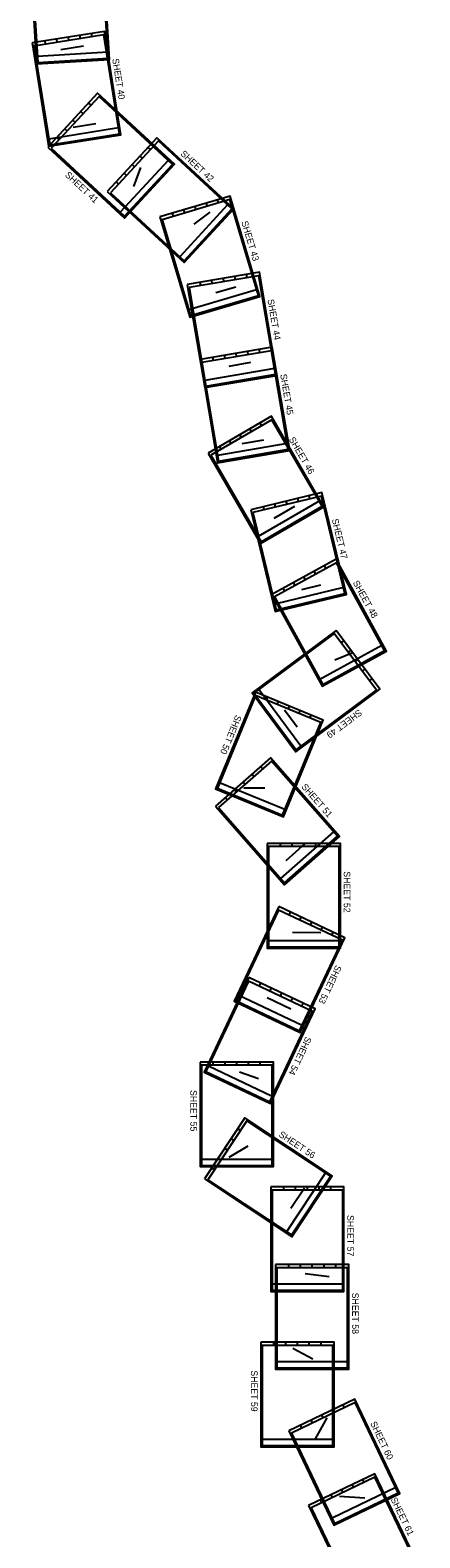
# Model space of a CAD drawing. Extents: x 518852 to 589310, y 1937169 to 2155394.
# Drawn here: x 550218 to 565119, y 1993000 to 2050636 of the extents above; entities that cross this region are included whole.
import ezdxf

# ---------------------------------------------------------------- set-up
doc = ezdxf.new("R2010")
doc.units = 0
doc.layers.add('Level 1', color=7, linetype='Continuous')
doc.layers.add('Level 58', color=7, linetype='Continuous')

msp = doc.modelspace()

# ---------------------------------------------------------------- linework, layer by layer
at = {"layer": 'Level 1'}
for p, q in [((550391, 2050518), (550441, 2050521)), ((550809, 2050100), (550790, 2050224)), ((551254, 2050171), (551234, 2050294)), ((551698, 2050242), (551679, 2050365)), ((552143, 2050312), (552123, 2050436)), ((552587, 2050383), (552567, 2050506)), ((553164, 2050238), (553213, 2050241)), ((550386, 2049577), (550436, 2049585)), ((550419, 2050069), (550469, 2050072)), ((553191, 2049789), (550496, 2049623)), ((552759, 2049486), (552756, 2049536)), ((553102, 2050009), (553152, 2050017)), ((553173, 2049565), (553222, 2049573)), ((550457, 2049133), (550506, 2049141)), ((550962, 2049376), (550959, 2049426)), ((551411, 2049404), (551408, 2049454)), ((551860, 2049431), (551857, 2049481)), ((552310, 2049459), (552307, 2049509)), ((553244, 2049120), (553293, 2049128)), ((550528, 2048688), (550577, 2048696)), ((553314, 2048676), (553364, 2048684)), ((550598, 2048244), (550648, 2048252)), ((550669, 2047799), (550719, 2047807)), ((552547, 2047771), (552455, 2047856)), ((553183, 2047796), (553217, 2047833)), ((553385, 2048232), (553434, 2048239)), ((550740, 2047355), (550789, 2047363)), ((552242, 2047441), (552150, 2047525)), ((553456, 2047787), (553505, 2047795)), ((553513, 2047490), (553547, 2047527)), ((553526, 2047343), (553576, 2047351)), ((550811, 2046911), (550860, 2046919)), ((553597, 2046898), (550931, 2046474)), ((551631, 2046780), (551539, 2046865)), ((551936, 2047110), (551844, 2047195)), ((553844, 2047185), (553878, 2047222)), ((554174, 2046879), (554208, 2046916)), ((551325, 2046449), (551233, 2046534)), ((551418, 2046273), (551411, 2046323)), ((551863, 2046344), (551855, 2046393)), ((552307, 2046415), (552299, 2046464)), ((552752, 2046485), (552744, 2046535)), ((553196, 2046556), (553188, 2046605)), ((554505, 2046574), (554539, 2046611)), ((554820, 2046071), (554728, 2046156)), ((554835, 2046268), (554869, 2046305)), ((555456, 2046096), (555490, 2046133)), ((551316, 2045777), (551350, 2045813)), ((551647, 2045471), (551680, 2045508)), ((555496, 2045657), (553663, 2043675)), ((554515, 2045740), (554423, 2045825)), ((555166, 2045963), (555199, 2046000)), ((555786, 2045790), (555820, 2045827)), ((556117, 2045485), (556151, 2045522)), ((551977, 2045166), (552011, 2045202)), ((553904, 2045080), (553812, 2045165)), ((554209, 2045410), (554117, 2045495)), ((555392, 2045140), (555356, 2045174)), ((556447, 2045179), (556481, 2045216)), ((552307, 2044860), (552341, 2044897)), ((552638, 2044555), (552672, 2044591)), ((553598, 2044749), (553506, 2044834)), ((554781, 2044479), (554745, 2044513)), ((555087, 2044810), (555050, 2044844)), ((556778, 2044874), (556812, 2044911)), ((557108, 2044568), (557142, 2044605)), ((552968, 2044249), (553002, 2044286)), ((553299, 2043944), (553332, 2043980)), ((553589, 2044077), (553623, 2044113)), ((553919, 2043771), (553953, 2043808)), ((554170, 2043819), (554134, 2043853)), ((554476, 2044149), (554439, 2044183)), ((557769, 2043957), (555936, 2041975)), ((556559, 2043775), (556524, 2043895)), ((556991, 2043903), (556955, 2044023)), ((557422, 2044031), (557386, 2044151)), ((557438, 2044263), (557472, 2044300)), ((554250, 2043466), (554284, 2043502)), ((554580, 2043160), (554614, 2043197)), ((555697, 2043518), (555661, 2043638)), ((556128, 2043647), (556092, 2043766)), ((557665, 2043440), (557629, 2043474)), ((557981, 2043728), (558029, 2043743)), ((558110, 2043297), (558158, 2043311)), ((554911, 2042855), (554945, 2042891)), ((555346, 2042945), (555393, 2042959)), ((557054, 2042779), (557018, 2042813)), ((557360, 2043110), (557323, 2043144)), ((558238, 2042866), (558286, 2042880)), ((555241, 2042549), (555275, 2042586)), ((555474, 2042513), (555522, 2042528)), ((555571, 2042244), (555605, 2042280)), ((555602, 2042082), (555650, 2042096)), ((556443, 2042119), (556407, 2042153)), ((556749, 2042449), (556712, 2042483)), ((558366, 2042434), (558414, 2042448)), ((555730, 2041651), (555778, 2041665)), ((558494, 2042003), (558542, 2042017)), ((558623, 2041572), (558671, 2041586)), ((555858, 2041219), (555906, 2041234)), ((556738, 2040873), (556717, 2040996)), ((557182, 2040948), (557161, 2041071)), ((557626, 2041023), (557605, 2041147)), ((558069, 2041099), (558048, 2041222)), ((558513, 2041174), (558492, 2041298)), ((558751, 2041140), (558799, 2041154)), ((555987, 2040788), (556035, 2040802)), ((556115, 2040357), (556163, 2040371)), ((558879, 2040709), (556291, 2039939)), ((556321, 2040345), (556370, 2040353)), ((558526, 2040317), (558512, 2040365)), ((559032, 2040806), (559081, 2040815)), ((559107, 2040363), (559157, 2040371)), ((556396, 2039901), (556446, 2039910)), ((556801, 2039804), (556787, 2039852)), ((557232, 2039932), (557218, 2039980)), ((557663, 2040061), (557649, 2040108)), ((558095, 2040189), (558081, 2040237)), ((559183, 2039919), (559232, 2039927)), ((556472, 2039458), (556521, 2039466)), ((559258, 2039475), (559308, 2039484)), ((556547, 2039014), (556597, 2039023)), ((559334, 2039032), (559383, 2039040)), ((559409, 2038588), (559459, 2038597)), ((556623, 2038571), (556672, 2038579)), ((556698, 2038127), (556748, 2038135)), ((557227, 2038005), (557206, 2038128)), ((557670, 2038080), (557649, 2038204)), ((558114, 2038156), (558093, 2038279)), ((558557, 2038231), (558537, 2038355)), ((559001, 2038307), (558980, 2038430)), ((559485, 2038145), (559534, 2038153)), ((556774, 2037683), (556823, 2037692)), ((556809, 2037477), (556858, 2037486)), ((559560, 2037701), (556899, 2037248)), ((559520, 2037939), (559570, 2037947)), ((559596, 2037495), (559645, 2037504)), ((556885, 2037034), (556934, 2037042)), ((557388, 2037052), (557380, 2037102)), ((557832, 2037128), (557824, 2037177)), ((558276, 2037203), (558267, 2037253)), ((558719, 2037279), (558711, 2037328)), ((559163, 2037354), (559154, 2037404)), ((559671, 2037051), (559720, 2037060)), ((556960, 2036590), (557009, 2036599)), ((559747, 2036608), (559796, 2036616)), ((557036, 2036147), (557085, 2036155)), ((557111, 2035703), (557160, 2035711)), ((559822, 2036164), (559871, 2036173)), ((559898, 2035721), (559947, 2035729)), ((557187, 2035259), (557236, 2035268)), ((558296, 2035064), (558234, 2035172)), ((558686, 2035290), (558623, 2035398)), ((559075, 2035516), (559012, 2035624)), ((559690, 2035352), (559733, 2035377)), ((559973, 2035277), (560022, 2035285)), ((557262, 2034816), (557311, 2034824)), ((560049, 2034833), (557387, 2034380)), ((557518, 2034613), (557455, 2034721)), ((557907, 2034839), (557844, 2034947)), ((559916, 2034963), (559959, 2034988)), ((560141, 2034574), (560185, 2034599)), ((557311, 2033973), (557354, 2033998)), ((557877, 2034185), (557868, 2034234)), ((558320, 2034260), (558312, 2034310)), ((558764, 2034336), (558755, 2034385)), ((559207, 2034411), (559199, 2034461)), ((559651, 2034487), (559643, 2034536)), ((560367, 2034185), (560411, 2034210)), ((557537, 2033583), (557580, 2033608)), ((560593, 2033795), (560636, 2033820)), ((560819, 2033406), (560862, 2033431)), ((557763, 2033194), (557806, 2033219)), ((557988, 2032805), (558032, 2032830)), ((560918, 2032720), (560889, 2032841)), ((561045, 2033017), (561088, 2033042)), ((558214, 2032416), (558257, 2032441)), ((561270, 2032627), (558935, 2031273)), ((559167, 2032300), (559138, 2032421)), ((559605, 2032405), (559576, 2032526)), ((560043, 2032510), (560013, 2032631)), ((560480, 2032615), (560451, 2032736)), ((561460, 2032387), (561509, 2032399)), ((558440, 2032026), (558483, 2032051)), ((558786, 2031746), (558835, 2031757)), ((560241, 2031712), (560215, 2031756)), ((560630, 2031938), (560605, 2031981)), ((561019, 2032164), (560994, 2032207)), ((561565, 2031949), (561614, 2031961)), ((558666, 2031637), (558709, 2031662)), ((558891, 2031308), (558940, 2031320)), ((559462, 2031261), (559437, 2031304)), ((559851, 2031487), (559826, 2031530)), ((561670, 2031512), (561719, 2031523)), ((558996, 2030870), (559045, 2030882)), ((561775, 2031074), (561824, 2031086)), ((561880, 2030637), (561929, 2030648)), ((559101, 2030433), (559150, 2030445)), ((559206, 2029995), (559254, 2030007)), ((561142, 2029840), (561081, 2029950)), ((561536, 2030057), (561476, 2030166)), ((561985, 2030199), (562034, 2030211)), ((559311, 2029558), (559359, 2029569)), ((560353, 2029407), (560293, 2029516)), ((560747, 2029623), (560687, 2029733)), ((562090, 2029761), (562139, 2029773)), ((562147, 2029879), (562191, 2029903)), ((562364, 2029484), (562408, 2029508)), ((559416, 2029120), (559464, 2029132)), ((562195, 2029324), (559569, 2028694)), ((559958, 2029190), (559898, 2029300)), ((560946, 2028742), (560935, 2028790)), ((561384, 2028847), (561372, 2028895)), ((561821, 2028951), (561810, 2029000)), ((562580, 2029090), (562624, 2029114)), ((559737, 2028555), (559780, 2028579)), ((560071, 2028532), (560059, 2028580)), ((560509, 2028637), (560497, 2028685)), ((562797, 2028695), (562841, 2028719)), ((563013, 2028301), (563057, 2028325)), ((559953, 2028161), (559997, 2028185)), ((560170, 2027766), (560214, 2027790)), ((563230, 2027907), (563274, 2027931)), ((560386, 2027372), (560430, 2027396)), ((561094, 2027076), (561124, 2027036)), ((563663, 2027118), (561297, 2025818)), ((561455, 2027345), (561485, 2027304)), ((562115, 2027212), (562215, 2027286)), ((563447, 2027512), (563490, 2027536)), ((560372, 2026539), (560401, 2026499)), ((560603, 2026977), (560647, 2027001)), ((560733, 2026808), (560763, 2026767)), ((560820, 2026583), (560863, 2026607)), ((562383, 2026851), (562483, 2026925)), ((562651, 2026489), (562752, 2026564)), ((563007, 2026443), (562983, 2026487)), ((563401, 2026660), (563377, 2026704)), ((559649, 2026002), (559679, 2025962)), ((560010, 2026271), (560040, 2026231)), ((561036, 2026188), (561080, 2026213)), ((562218, 2026010), (562194, 2026054)), ((562612, 2026227), (562588, 2026271)), ((562920, 2026128), (563020, 2026203)), ((560568, 2023258), (558957, 2025425)), ((559288, 2025734), (559318, 2025694)), ((561823, 2025794), (561799, 2025837)), ((563188, 2025767), (563289, 2025842)), ((558617, 2024798), (558663, 2024779)), ((559005, 2024900), (559045, 2024930)), ((559251, 2025023), (559299, 2025139)), ((559667, 2024851), (559715, 2024967)), ((560083, 2024680), (560131, 2024795)), ((562735, 2024869), (562764, 2024829)), ((563096, 2025138), (563125, 2025097)), ((558446, 2024382), (558492, 2024363)), ((559273, 2024539), (559313, 2024569)), ((559542, 2024178), (559582, 2024207)), ((560499, 2024508), (560547, 2024624)), ((560915, 2024337), (560963, 2024452)), ((562012, 2024332), (562042, 2024292)), ((562373, 2024601), (562403, 2024560)), ((558274, 2023966), (558320, 2023947)), ((559810, 2023817), (559850, 2023846)), ((561159, 2023749), (561206, 2023730)), ((561290, 2023795), (561320, 2023755)), ((561651, 2024064), (561681, 2024024)), ((557931, 2023134), (557977, 2023115)), ((558102, 2023550), (558149, 2023531)), ((560078, 2023455), (560119, 2023485)), ((560929, 2023527), (560959, 2023487)), ((560988, 2023333), (561034, 2023314)), ((557759, 2022718), (557805, 2022699)), ((559110, 2022398), (559027, 2022492)), ((560645, 2022501), (560691, 2022482)), ((560816, 2022917), (560862, 2022898)), ((557588, 2022302), (557634, 2022283)), ((558434, 2021805), (558351, 2021899)), ((558772, 2022102), (558689, 2022195)), ((559745, 2022357), (559783, 2022390)), ((560042, 2022019), (560079, 2022052)), ((560473, 2022085), (560519, 2022066)), ((559958, 2020837), (557462, 2021867)), ((557757, 2021211), (557675, 2021305)), ((557773, 2021441), (557792, 2021487)), ((558096, 2021508), (558013, 2021602)), ((558189, 2021269), (558208, 2021316)), ((560301, 2021669), (560348, 2021650)), ((560339, 2021681), (560376, 2021714)), ((560636, 2021343), (560673, 2021376)), ((558605, 2021098), (558624, 2021144)), ((559021, 2020926), (559040, 2020972)), ((559437, 2020754), (559456, 2020801)), ((560130, 2021253), (560176, 2021234)), ((560933, 2021005), (560970, 2021038)), ((557679, 2020543), (557716, 2020576)), ((557976, 2020205), (558013, 2020238)), ((561230, 2020667), (561267, 2020700)), ((561527, 2020328), (561564, 2020361)), ((558272, 2019866), (558310, 2019899)), ((561823, 2019990), (559795, 2018209)), ((558569, 2019528), (558607, 2019561)), ((558866, 2019190), (558904, 2019223)), ((559785, 2019423), (559785, 2019548)), ((560235, 2019423), (560235, 2019548)), ((560685, 2019423), (560685, 2019548)), ((561135, 2019423), (561135, 2019548)), ((561329, 2019190), (561296, 2019227)), ((561585, 2019423), (561585, 2019548)), ((561667, 2019487), (561634, 2019524)), ((559163, 2018852), (559201, 2018885)), ((559285, 2018973), (559335, 2018973)), ((559285, 2018523), (559335, 2018523)), ((559460, 2018514), (559498, 2018547)), ((560652, 2018596), (560619, 2018634)), ((560991, 2018893), (560958, 2018930)), ((562035, 2018973), (562085, 2018973)), ((562035, 2018523), (562085, 2018523)), ((559285, 2018073), (559335, 2018073)), ((560314, 2018299), (560281, 2018337)), ((562035, 2018073), (562085, 2018073)), ((559285, 2017623), (559335, 2017623)), ((562035, 2017623), (562085, 2017623)), ((559285, 2017173), (559335, 2017173)), ((559285, 2016723), (559335, 2016723)), ((560121, 2016805), (560175, 2016918)), ((560528, 2016613), (560582, 2016726)), ((562035, 2017173), (562085, 2017173)), ((562035, 2016723), (562085, 2016723)), ((559285, 2016273), (559335, 2016273)), ((559285, 2016205), (559330, 2016184)), ((559477, 2016612), (559522, 2016590)), ((560935, 2016420), (560988, 2016533)), ((561342, 2016228), (561395, 2016341)), ((561749, 2016036), (561802, 2016149)), ((562035, 2016273), (562085, 2016273)), ((559092, 2015798), (559138, 2015777)), ((562035, 2015823), (559335, 2015823)), ((559785, 2015548), (559785, 2015598)), ((560235, 2015548), (560235, 2015598)), ((560685, 2015548), (560685, 2015598)), ((561135, 2015548), (561135, 2015598)), ((561585, 2015548), (561585, 2015598)), ((558708, 2014984), (558753, 2014963)), ((558900, 2015391), (558945, 2015370)), ((561771, 2015030), (561816, 2015008)), ((561963, 2015437), (562009, 2015415)), ((558516, 2014578), (558561, 2014556)), ((561579, 2014623), (561624, 2014602)), ((558323, 2014171), (558369, 2014149)), ((558335, 2013895), (558380, 2013873)), ((558980, 2014088), (559033, 2014201)), ((559386, 2013896), (559440, 2014009)), ((559793, 2013703), (559847, 2013816)), ((561194, 2013809), (561239, 2013788)), ((561386, 2014216), (561432, 2014195)), ((558143, 2013488), (558188, 2013467)), ((560617, 2012589), (558176, 2013742)), ((558466, 2013302), (558487, 2013347)), ((560200, 2013511), (560254, 2013624)), ((560607, 2013319), (560660, 2013432)), ((561002, 2013402), (561047, 2013381)), ((557758, 2012674), (557804, 2012653)), ((557951, 2013081), (557996, 2013060)), ((558872, 2013109), (558894, 2013154)), ((559279, 2012917), (559301, 2012962)), ((559686, 2012725), (559707, 2012770)), ((560810, 2012996), (560855, 2012974)), ((560822, 2012720), (560867, 2012698)), ((557566, 2012267), (557611, 2012246)), ((560093, 2012532), (560114, 2012578)), ((560629, 2012313), (560674, 2012292)), ((557374, 2011861), (557419, 2011839)), ((560245, 2011499), (560290, 2011478)), ((560437, 2011906), (560482, 2011885)), ((559475, 2009872), (557034, 2011026)), ((557181, 2011454), (557227, 2011432)), ((557219, 2011065), (557219, 2011190)), ((557669, 2011065), (557669, 2011190)), ((558119, 2011065), (558119, 2011190)), ((558569, 2011065), (558569, 2011190)), ((559019, 2011065), (559019, 2011190)), ((560052, 2011092), (560098, 2011071)), ((556719, 2010615), (556769, 2010615)), ((557324, 2010585), (557345, 2010630)), ((557731, 2010392), (557752, 2010438)), ((559469, 2010615), (559519, 2010615)), ((559860, 2010686), (559905, 2010664)), ((556719, 2010165), (556769, 2010165)), ((558137, 2010200), (558159, 2010245)), ((558544, 2010008), (558566, 2010053)), ((558951, 2009815), (558972, 2009861)), ((559469, 2010165), (559519, 2010165)), ((559668, 2010279), (559713, 2010257)), ((556719, 2009715), (556769, 2009715)), ((556719, 2009265), (556769, 2009265)), ((559469, 2009715), (559519, 2009715)), ((559469, 2009265), (559519, 2009265)), ((556719, 2008815), (556769, 2008815)), ((558260, 2008567), (558156, 2008636)), ((558884, 2008693), (558912, 2008735)), ((559469, 2008815), (559519, 2008815)), ((556719, 2008365), (556769, 2008365)), ((558012, 2008191), (557907, 2008260)), ((559259, 2008445), (559287, 2008486)), ((559469, 2008365), (559519, 2008365)), ((559634, 2008196), (559662, 2008238)), ((556719, 2007915), (556769, 2007915)), ((559469, 2007465), (556769, 2007465)), ((557515, 2007441), (557410, 2007510)), ((557763, 2007816), (557659, 2007885)), ((559469, 2007915), (559519, 2007915)), ((560009, 2007948), (560037, 2007989)), ((560384, 2007699), (560412, 2007741)), ((560760, 2007450), (560787, 2007492)), ((557266, 2007066), (557162, 2007135)), ((557219, 2007190), (557219, 2007240)), ((557669, 2007190), (557669, 2007240)), ((558119, 2007190), (558119, 2007240)), ((558569, 2007190), (558569, 2007240)), ((559019, 2007190), (559019, 2007240)), ((561510, 2006953), (560019, 2004703)), ((561135, 2007202), (561162, 2007244)), ((557365, 2006401), (557393, 2006442)), ((559918, 2006293), (559918, 2006418)), ((560368, 2006293), (560368, 2006418)), ((560818, 2006293), (560818, 2006418)), ((561268, 2006293), (561268, 2006418)), ((561491, 2006426), (561449, 2006454)), ((561718, 2006293), (561718, 2006418)), ((557740, 2006152), (557768, 2006194)), ((558115, 2005904), (558143, 2005945)), ((559418, 2005843), (559468, 2005843)), ((561242, 2006051), (561200, 2006079)), ((562168, 2005843), (562218, 2005843)), ((558491, 2005655), (558518, 2005697)), ((558866, 2005406), (558893, 2005448)), ((559241, 2005158), (559268, 2005200)), ((559418, 2005393), (559468, 2005393)), ((560745, 2005301), (560703, 2005329)), ((560994, 2005676), (560952, 2005704)), ((562168, 2005393), (562218, 2005393)), ((559418, 2004943), (559468, 2004943)), ((559616, 2004909), (559644, 2004951)), ((560496, 2004926), (560455, 2004953)), ((562168, 2004943), (562218, 2004943)), ((559418, 2004493), (559468, 2004493)), ((559418, 2004043), (559468, 2004043)), ((562168, 2004493), (562218, 2004493)), ((562168, 2004043), (562218, 2004043)), ((559418, 2003593), (559468, 2003593)), ((560104, 2003323), (560104, 2003448)), ((560554, 2003323), (560554, 2003448)), ((561004, 2003323), (561004, 2003448)), ((561454, 2003323), (561454, 2003448)), ((561904, 2003323), (561904, 2003448)), ((562168, 2003593), (562218, 2003593)), ((559418, 2003143), (559468, 2003143)), ((559604, 2002873), (559654, 2002873)), ((562168, 2003143), (562218, 2003143)), ((562354, 2002873), (562404, 2002873)), ((562168, 2002693), (559468, 2002693)), ((559604, 2002423), (559654, 2002423)), ((559918, 2002418), (559918, 2002468)), ((560368, 2002418), (560368, 2002468)), ((560818, 2002418), (560818, 2002468)), ((561268, 2002418), (561268, 2002468)), ((561718, 2002418), (561718, 2002468)), ((562354, 2002423), (562404, 2002423)), ((559604, 2001973), (559654, 2001973)), ((562354, 2001973), (562404, 2001973)), ((559604, 2001523), (559654, 2001523)), ((562354, 2001523), (562404, 2001523)), ((559604, 2001073), (559654, 2001073)), ((559604, 2000623), (559654, 2000623)), ((562354, 2001073), (562404, 2001073)), ((562354, 2000623), (562404, 2000623)), ((559541, 2000358), (559541, 2000483)), ((559604, 2000173), (559654, 2000173)), ((559991, 2000358), (559991, 2000483)), ((560441, 2000358), (560441, 2000483)), ((560891, 2000358), (560891, 2000483)), ((561341, 2000358), (561341, 2000483)), ((562354, 2000173), (562404, 2000173)), ((559041, 1999908), (559091, 1999908)), ((559041, 1999458), (559091, 1999458)), ((562354, 1999723), (559654, 1999723)), ((560104, 1999448), (560104, 1999498)), ((560554, 1999448), (560554, 1999498)), ((561004, 1999448), (561004, 1999498)), ((561454, 1999448), (561454, 1999498)), ((561791, 1999908), (561841, 1999908)), ((561791, 1999458), (561841, 1999458)), ((561904, 1999448), (561904, 1999498)), ((559041, 1999008), (559091, 1999008)), ((561791, 1999008), (561841, 1999008)), ((559041, 1998558), (559091, 1998558)), ((561791, 1998558), (561841, 1998558)), ((559041, 1998108), (559091, 1998108)), ((561423, 1997587), (561369, 1997700)), ((561829, 1997781), (561775, 1997894)), ((561791, 1998108), (561841, 1998108)), ((562235, 1997976), (562181, 1998088)), ((562835, 1997764), (562880, 1997786)), ((559041, 1997658), (559091, 1997658)), ((559041, 1997208), (559091, 1997208)), ((560611, 1997198), (560557, 1997311)), ((561017, 1997393), (560963, 1997506)), ((561791, 1997658), (561841, 1997658)), ((561791, 1997208), (561841, 1997208)), ((563029, 1997358), (563074, 1997380)), ((561791, 1996758), (559091, 1996758)), ((559541, 1996483), (559541, 1996533)), ((559991, 1996483), (559991, 1996533)), ((560354, 1996577), (560400, 1996598)), ((560441, 1996483), (560441, 1996533)), ((560891, 1996483), (560891, 1996533)), ((561341, 1996483), (561341, 1996533)), ((563223, 1996952), (563269, 1996974)), ((563418, 1996546), (563463, 1996568)), ((560549, 1996171), (560594, 1996192)), ((563612, 1996140), (563657, 1996162)), ((560743, 1995765), (560788, 1995787)), ((560937, 1995359), (560982, 1995381)), ((563806, 1995735), (563851, 1995756)), ((561132, 1994953), (561177, 1994975)), ((564195, 1994923), (561760, 1993757)), ((562183, 1994733), (562129, 1994846)), ((562589, 1994927), (562535, 1995040)), ((562995, 1995122), (562941, 1995235)), ((563595, 1994910), (563640, 1994932)), ((564001, 1995329), (564046, 1995350)), ((561371, 1994345), (561317, 1994457)), ((561326, 1994547), (561371, 1994569)), ((561777, 1994539), (561723, 1994652)), ((563502, 1994286), (563480, 1994331)), ((563789, 1994504), (563834, 1994526)), ((563908, 1994480), (563886, 1994526)), ((561114, 1993723), (561159, 1993744)), ((561520, 1994141), (561565, 1994163)), ((562284, 1993703), (562263, 1993748)), ((562690, 1993898), (562668, 1993943)), ((563096, 1994092), (563074, 1994137)), ((563983, 1994098), (564028, 1994120)), ((564178, 1993692), (564223, 1993714)), ((561309, 1993317), (561354, 1993339)), ((564372, 1993287), (564417, 1993308))]:
    msp.add_line(p, q, dxfattribs=at)
for points in [[(550218, 2053338), (550463, 2049346), (553258, 2049517), (553013, 2053510)], [(550276, 2053216), (550510, 2049398), (553205, 2049564), (552970, 2053382)], [(550296, 2050145), (550925, 2046195), (553690, 2046635), (553061, 2050585)], [(550365, 2050029), (550966, 2046252), (553633, 2046676), (553031, 2050454)], [(550894, 2046167), (553831, 2043452), (555732, 2045507), (552795, 2048223)], [(551020, 2046119), (553828, 2043522), (555661, 2045505), (552853, 2048101)], [(553167, 2044467), (556104, 2041751), (558005, 2043807), (555068, 2046523)], [(553293, 2044419), (556101, 2041822), (557934, 2043805), (555126, 2046401)], [(555182, 2043496), (556321, 2039662), (559005, 2040460), (557866, 2044294)], [(555265, 2043390), (556355, 2039724), (558943, 2040493), (557853, 2044160)], [(556225, 2040912), (556895, 2036969), (559656, 2037438), (558985, 2041382)], [(556295, 2040797), (556936, 2037026), (559598, 2037479), (558957, 2041250)], [(556713, 2038044), (557384, 2034101), (560144, 2034571), (559473, 2038514)], [(556783, 2037929), (557425, 2034159), (560086, 2034612), (559445, 2038382)], [(557023, 2034470), (559029, 2031010), (561452, 2032415), (559445, 2035875)], [(557129, 2034387), (559048, 2031078), (561383, 2032433), (559464, 2035742)], [(558652, 2032305), (559585, 2028415), (562308, 2029068), (561375, 2032958)], [(558730, 2032195), (559622, 2028475), (562247, 2029105), (561355, 2032825)], [(559460, 2029059), (561385, 2025553), (563839, 2026901), (561914, 2030407)], [(559564, 2028974), (561405, 2025621), (563772, 2026920), (561931, 2030273)], [(561917, 2027688), (558706, 2025301), (560377, 2023054), (563587, 2025440)], [(561846, 2027573), (558776, 2025291), (560387, 2023124), (563457, 2025406)], [(558837, 2025329), (557311, 2021632), (559899, 2020564), (561425, 2024261)], [(558835, 2025195), (557376, 2021659), (559872, 2020629), (561331, 2024165)], [(557299, 2020975), (559939, 2017969), (562042, 2019817), (559403, 2022822)], [(557419, 2020914), (559943, 2018040), (561972, 2019821), (559448, 2022695)], [(559285, 2019548), (559285, 2015548), (562085, 2015548), (562085, 2019548)], [(559335, 2019423), (559335, 2015598), (562035, 2015598), (562035, 2019423)], [(559723, 2017132), (558014, 2013515), (560545, 2012319), (562254, 2015935)], [(559715, 2016997), (558080, 2013539), (560521, 2012385), (562156, 2015844)], [(558581, 2014415), (556872, 2010798), (559403, 2009602), (561112, 2013218)], [(558573, 2014280), (556938, 2010822), (559379, 2009668), (561014, 2013127)], [(556719, 2011190), (556719, 2007190), (559519, 2007190), (559519, 2011190)], [(556769, 2011065), (556769, 2007240), (559469, 2007240), (559469, 2011065)], [(556886, 2006718), (560220, 2004509), (561767, 2006843), (558432, 2009052)], [(557018, 2006691), (560206, 2004578), (561697, 2006829), (558509, 2008942)], [(559418, 2006418), (559418, 2002418), (562218, 2002418), (562218, 2006418)], [(559468, 2006293), (559468, 2002468), (562168, 2002468), (562168, 2006293)], [(559604, 2003448), (559604, 1999448), (562404, 1999448), (562404, 2003448)], [(559654, 2003323), (559654, 1999498), (562354, 1999498), (562354, 2003323)], [(559041, 2000483), (559041, 1996483), (561841, 1996483), (561841, 2000483)], [(559091, 2000358), (559091, 1996533), (561791, 1996533), (561791, 2000358)], [(560106, 1997095), (561833, 1993487), (564359, 1994696), (562632, 1998304)], [(560205, 1997004), (561857, 1993554), (564292, 1994720), (562641, 1998170)], [(560866, 1994241), (562593, 1990634), (565119, 1991842), (563392, 1995450)], [(560965, 1994150), (562617, 1990700), (565052, 1991866), (563400, 1995316)]]:
    msp.add_lwpolyline(points, close=True, dxfattribs=at)
at = {"layer": 'Level 58'}
for p, q in [((551389, 2049894), (552254, 2050032)), ((551860, 2046931), (552726, 2047069)), ((554181, 2044655), (554453, 2045385)), ((556488, 2043220), (557100, 2043673)), ((557315, 2040601), (558080, 2040828)), ((557828, 2037797), (558655, 2037938)), ((558331, 2034840), (559158, 2034980)), ((559545, 2031976), (560341, 2032437)), ((560611, 2029257), (561329, 2029429)), ((561869, 2026560), (562560, 2026848)), ((559942, 2024650), (560427, 2023998)), ((558393, 2021666), (559191, 2021674)), ((560009, 2018895), (560741, 2019555)), ((560252, 2016159), (561334, 2016143)), ((559281, 2013650), (560187, 2013221)), ((558220, 2010814), (558954, 2010559)), ((557829, 2007556), (558558, 2007988)), ((560182, 2005600), (560704, 2006386)), ((560733, 2003108), (561657, 2002989)), ((560266, 2000247), (561025, 1999841)), ((561124, 1996784), (561572, 1997584)), ((562052, 1994594), (563011, 1994528))]:
    msp.add_line(p, q, dxfattribs=at)

# ---------------------------------------------------------------- texts
for s, rotation, p in [('SHEET 40', 279.04184, (553355, 2049534)), ('SHEET 42', 317.24288, (555943, 2045884)), ('SHEET 41', 317.24286, (551529, 2045072)), ('SHEET 43', 286.55619, (558291, 2043300)), ('SHEET 44', 279.65594, (559291, 2040330)), ('SHEET 45', 279.65594, (559777, 2037471)), ('SHEET 46', 300.11344, (560098, 2034997)), ('SHEET 47', 283.48625, (561750, 2031931)), ('SHEET 48', 298.77067, (562546, 2029516)), ('SHEET 50', 247.58088, (558080, 2024478)), ('SHEET 49', 216.62545, (562789, 2024691)), ('SHEET 51', 311.28743, (560572, 2021698)), ('SHEET 52', 270.00001, (562210, 2018480)), ('SHEET 53', 244.70305, (561912, 2014918)), ('SHEET 54', 244.70305, (560764, 2012189)), ('SHEET 55', 269.99999, (556344, 2010118)), ('SHEET 56', 326.47523, (559701, 2008360)), ('SHEET 57', 270.00001, (562343, 2005340)), ('SHEET 58', 270.00001, (562529, 2002371)), ('SHEET 59', 269.99999, (558666, 1999404)), ('SHEET 60', 295.57888, (563212, 1997381)), ('SHEET 61', 295.57888, (563996, 1994477))]:
    msp.add_text(s, height=250, rotation=rotation, dxfattribs=at).set_placement(p)

doc.saveas('drawing.dxf')
